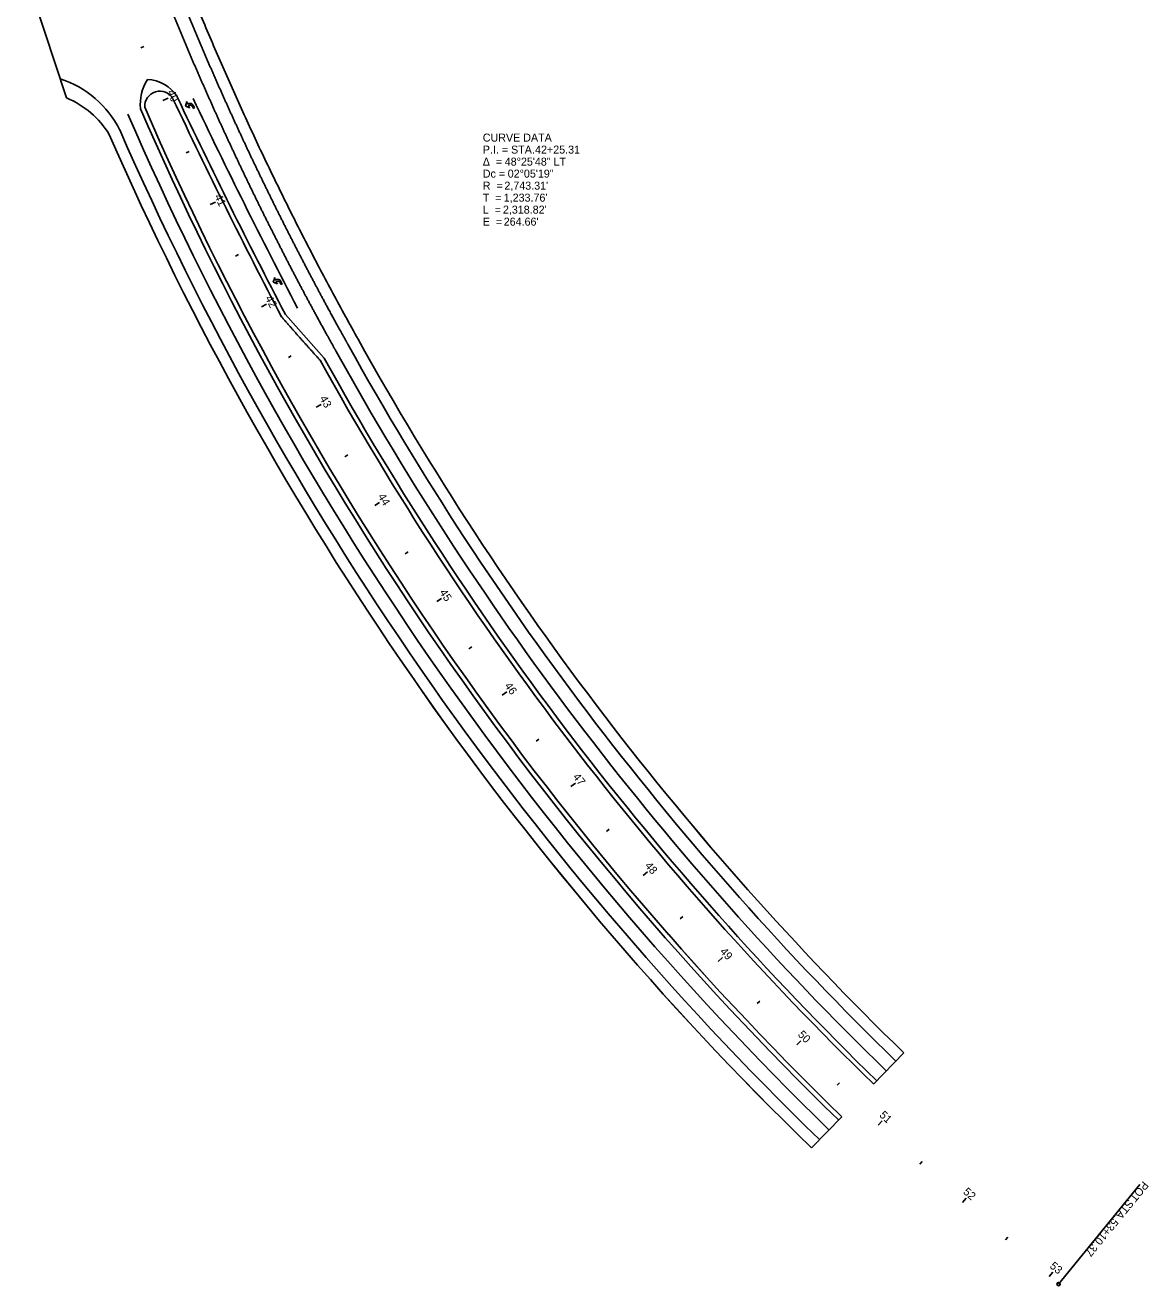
# Model space of a CAD drawing. Extents: x 76539 to 88870, y 518807 to 527554.
# Drawn here: x 87834 to 88817, y 518807 to 519909 of the extents above; entities that cross this region are included whole.
import ezdxf

# ---------------------------------------------------------------- set-up
doc = ezdxf.new("R2010")
doc.units = 0
for name, color, linetype in [('Default', 7, 'Continuous'), ('GE_P_Alignment_100_Cardinal_Points', 7, 'Continuous'), ('GE_P_Alignment_100_Curve_Data', 7, 'Continuous'), ('GE_P_Alignment_100_Stations', 7, 'Continuous'), ('PM_P_Cells', 7, 'Continuous'), ('PM_P_Channelizing_Line', 7, 'Continuous'), ('PM_P_Edge_Line', 7, 'Continuous'), ('PM_P_Lane_Line', 7, 'Continuous'), ('PV_P_Joint', 7, 'Continuous'), ('PV_P_Shoulder', 7, 'Continuous'), ('XS_P_Pavt_Surface', 7, 'Continuous')]:
    doc.layers.add(name, color=color, linetype=linetype)

msp = doc.modelspace()

# ---------------------------------------------------------------- linework, layer by layer
at = {"layer": 'Default'}
for points, degree in [([(87936.8, 520051.1), (87939.4, 520044), (87944.5, 520029.6), (87952.4, 520008.1), (87960.5, 519986.7), (87968.8, 519965.3), (87977.2, 519944), (87985.9, 519922.8), (87994.7, 519901.7), (88003.7, 519880.6), (88012.9, 519859.7), (88022.3, 519838.8), (88031.8, 519817.9), (88041.5, 519797.2), (88051.4, 519776.6), (88061.5, 519756), (88071.7, 519735.5), (88082.1, 519715.1), (88092.7, 519694.9), (88103.5, 519674.7), (88114.4, 519654.5), (88121.8, 519641.2), (88125.5, 519634.5)], 3), ([(87916.1, 520043.7), (87917.5, 520039.7), (87922.6, 520025.4), (87932.1, 519999.5), (87939.9, 519979), (87948.3, 519957.2), (87956.8, 519935.9), (87965.5, 519914.5), (87974.4, 519893.2), (87983.5, 519871.9), (87992.8, 519850.8), (88002.2, 519829.7), (88011.8, 519808.8), (88021.6, 519787.9), (88031.6, 519767), (88041.7, 519746.3), (88052.1, 519725.7), (88062.5, 519705.2), (88073.3, 519684.4), (88083.6, 519665.1), (88096.8, 519640.9), (88104.2, 519627.6), (88106.3, 519623.9)], 2), ([(87927.4, 520047.8), (87928.8, 520043.7), (87933.9, 520029.5), (87943.4, 520003.7), (87951.1, 519983.3), (87959.5, 519961.6), (87967.9, 519940.3), (87976.6, 519919), (87985.5, 519897.8), (87994.5, 519876.7), (88003.7, 519855.7), (88013.1, 519834.7), (88022.7, 519813.8), (88032.4, 519793), (88042.4, 519772.3), (88052.5, 519751.6), (88062.8, 519731.1), (88073.2, 519710.7), (88084, 519690), (88094.2, 519670.8), (88107.3, 519646.6), (88114.7, 519633.5), (88116.8, 519629.7)], 2)]:
    msp.add_open_spline(points, degree=degree, dxfattribs=at)
at = {"layer": 'GE_P_Alignment_100_Cardinal_Points'}
msp.add_line((88737.9, 518808.1), (88809, 518895.3), dxfattribs=at)
msp.add_circle((88737.9, 518808.1), 1.5, dxfattribs=at)
at = {"layer": 'GE_P_Alignment_100_Stations'}
for p, q in [((87935.4, 519889.3), (87938.2, 519890.5)), ((87954.8, 519843.3), (87959.4, 519845.3)), ((87975.1, 519797.6), (87977.9, 519798.8)), ((87996.2, 519752.3), (88000.8, 519754.4)), ((88018.2, 519707.3), (88020.9, 519708.7)), ((88040.9, 519662.8), (88045.4, 519665.1)), ((88064.5, 519618.7), (88067.1, 519620.1)), ((88088.9, 519575.1), (88093.2, 519577.5)), ((88114, 519531.8), (88116.6, 519533.4)), ((88140, 519489.1), (88144.2, 519491.7)), ((88166.7, 519446.8), (88169.2, 519448.5)), ((88194.2, 519405.1), (88198.3, 519407.8)), ((88222.4, 519363.8), (88224.9, 519365.5)), ((88251.4, 519323.1), (88255.4, 519326)), ((88281.1, 519282.9), (88283.5, 519284.7)), ((88311.6, 519243.2), (88315.5, 519246.3)), ((88342.7, 519204.1), (88345.1, 519206)), ((88374.6, 519165.6), (88378.4, 519168.8)), ((88407.2, 519127.6), (88409.4, 519129.6)), ((88440.4, 519090.3), (88444.1, 519093.7)), ((88474.4, 519053.6), (88476.6, 519055.6)), ((88509, 519017.5), (88512.5, 519021)), ((88544.2, 518982), (88546.3, 518984.2)), ((88580.1, 518947.2), (88583.6, 518950.8)), ((88616.6, 518913.1), (88618.7, 518915.3)), ((88653.8, 518879.6), (88657.1, 518883.3)), ((88691.5, 518846.8), (88693.4, 518849.1)), ((88729.8, 518814.7), (88733, 518818.5))]:
    msp.add_line(p, q, dxfattribs=at)
at = {"layer": 'PM_P_Cells'}
for p, q in [((87975.9, 519842.5), (87974.5, 519838.4)), ((87975.9, 519842.5), (87975.9, 519842.5)), ((87976.3, 519840.2), (87975.9, 519842.5)), ((87974.5, 519838.4), (87978.3, 519836.9)), ((87976.9, 519840.5), (87976.3, 519840.2)), ((87977, 519838.8), (87977.6, 519839.1)), ((87978.3, 519836.9), (87977, 519838.8)), ((87979.4, 519835.3), (87979.4, 519835.3)), ((87980.7, 519838.1), (87981.5, 519836.4)), ((87982.4, 519836.8), (87981.3, 519839.1)), ((87981.5, 519836.4), (87982.4, 519836.8)), ((88052.6, 519688.5), (88051.3, 519684.4)), ((88052.6, 519688.5), (88052.6, 519688.5)), ((88053, 519686.2), (88052.6, 519688.5)), ((88051.3, 519684.4), (88055, 519682.9)), ((88053.6, 519686.5), (88053, 519686.2)), ((88053.7, 519684.8), (88054.3, 519685.1)), ((88055, 519682.9), (88053.7, 519684.8)), ((88056.2, 519681.3), (88056.2, 519681.3)), ((88057.4, 519684), (88058.3, 519682.4)), ((88059.1, 519682.8), (88058, 519685)), ((88058.3, 519682.4), (88059.1, 519682.8))]:
    msp.add_line(p, q, dxfattribs=at)
for centre, radius, end in [((87978.4, 519837.6), 3.28, 117.392), ((87978.6, 519837), 2.3, 116.4835), ((88055.1, 519683.6), 3.28, 117.392), ((88055.4, 519683), 2.3, 116.4835)]:
    msp.add_arc(centre, radius, 26.4835, end, dxfattribs=at)
at = {"layer": 'PM_P_Channelizing_Line'}
msp.add_arc((92717.6, 522090.4), 5241.6, 205.3632, 207.6038, dxfattribs=at)
at = {"layer": 'PM_P_Edge_Line'}
msp.add_line((88062, 519656.2), (88095.8, 519618.1), dxfattribs=at)
for centre, radius, start, end in [((87837.8, 519778), 88.6, 26.4768, 72.1065), ((87977.1, 519839.8), 42, 148.5921, 185.0887), ((87940.3, 519829.9), 31.8, 31.9322, 88.2373), ((92717.6, 522090.4), 5253.6, 205.2828, 207.6038), ((90472.1, 520933.7), 2764.1, 203.3971, 225.813), ((90472.1, 520933.7), 2788.1, 203.598, 225.813), ((90472.1, 520933.7), 2692.2, 208.9703, 225.8127), ((90472.1, 520933.7), 2716.2, 208.9703, 225.8127)]:
    msp.add_arc(centre, radius, start, end, dxfattribs=at)
at = {"layer": 'PM_P_Lane_Line'}
for radius, start, end in [(2776.1, 203.3971, 225.813), (2704.2, 208.9703, 225.8127)]:
    msp.add_arc((90472.1, 520933.7), radius, start, end, dxfattribs=at)
at = {"layer": 'PV_P_Joint'}
for p, q in [((87834.5, 519955), (87870.6, 519845.6)), ((88602.6, 519010.4), (88576.1, 518983.1)), ((88548.3, 518954.5), (88521.8, 518927.2))]:
    msp.add_line(p, q, dxfattribs=at)
at = {"layer": 'PV_P_Shoulder'}
for centre, radius, start, end in [((87840.4, 519772.6), 79, 31.2308, 67.5512), ((87952.2, 519838.2), 13.3, 30.6146, 182.6353), ((92717.6, 522090.4), 5257.6, 205.2828, 207.6038), ((90472.1, 520933.7), 2760.1, 203.3971, 225.813), ((90472.1, 520933.7), 2798.1, 203.598, 225.813), ((90472.1, 520933.7), 2682.2, 208.9703, 225.8127), ((90472.1, 520933.7), 2720.2, 208.9703, 225.8127)]:
    msp.add_arc(centre, radius, start, end, dxfattribs=at)
msp.add_open_spline([(88092.3, 519616.1), (88091.7, 519616.8), (88090.6, 519618), (88088.9, 519619.9), (88087.2, 519621.8), (88085.5, 519623.7), (88083.8, 519625.6), (88082.1, 519627.5), (88080.4, 519629.4), (88078.7, 519631.3), (88077, 519633.2), (88075.3, 519635.1), (88073.6, 519637), (88071.9, 519638.9), (88070.2, 519640.9), (88068.5, 519642.8), (88066.9, 519644.7), (88065.2, 519646.6), (88063.5, 519648.5), (88061.8, 519650.5), (88060.1, 519652.4), (88059, 519653.7), (88058.5, 519654.3)], degree=3, dxfattribs=at)
at = {"layer": 'XS_P_Pavt_Surface'}
for p, q in [((87870.6, 519845.6), (87834.5, 519955)), ((88602.6, 519010.4), (88576.1, 518983.1)), ((88548.3, 518954.5), (88521.8, 518927.2))]:
    msp.add_line(p, q, dxfattribs=at)
for centre, radius, start, end in [((87840.4, 519772.6), 79, 31.2308, 67.5512), ((87952.2, 519838.2), 13.3, 30.6146, 182.6353), ((92717.6, 522090.4), 5257.6, 205.2828, 207.6038), ((90472.1, 520933.7), 2760.1, 203.3971, 225.8131), ((90472.1, 520933.7), 2798.1, 203.598, 225.8133), ((90472.1, 520933.7), 2682.2, 208.9703, 225.8129), ((90472.1, 520933.7), 2720.2, 208.9703, 225.813)]:
    msp.add_arc(centre, radius, start, end, dxfattribs=at)
for points in [[(87936.8, 520051.1), (87939.4, 520044), (87944.5, 520029.6), (87952.4, 520008.1), (87960.5, 519986.7), (87968.8, 519965.3), (87977.2, 519944), (87985.9, 519922.8), (87994.7, 519901.7), (88003.7, 519880.6), (88012.9, 519859.7), (88022.3, 519838.8), (88031.8, 519817.9), (88041.5, 519797.2), (88051.4, 519776.6), (88061.5, 519756), (88071.7, 519735.5), (88082.1, 519715.1), (88092.7, 519694.9), (88103.5, 519674.7), (88114.4, 519654.5), (88121.8, 519641.2), (88125.5, 519634.5)], [(88092.3, 519616.1), (88091.7, 519616.8), (88090.6, 519618), (88088.9, 519619.9), (88087.2, 519621.8), (88085.5, 519623.7), (88083.8, 519625.6), (88082.1, 519627.5), (88080.4, 519629.4), (88078.7, 519631.3), (88077, 519633.2), (88075.3, 519635.1), (88073.6, 519637), (88071.9, 519638.9), (88070.2, 519640.9), (88068.5, 519642.8), (88066.9, 519644.7), (88065.2, 519646.6), (88063.5, 519648.5), (88061.8, 519650.5), (88060.1, 519652.4), (88059, 519653.7), (88058.5, 519654.3)]]:
    msp.add_open_spline(points, degree=3, dxfattribs=at)

# ---------------------------------------------------------------- texts
at = {"layer": 'GE_P_Alignment_100_Cardinal_Points'}
for s, p in [('POT', (88811.8, 518898.6)), (' STA. ', (88800.4, 518884.7)), ('53+10.37', (88785.5, 518866.3))]:
    msp.add_text(s, height=7, rotation=230.7887, dxfattribs=at).set_placement(p)
at = {"layer": 'GE_P_Alignment_100_Curve_Data'}
for s, p in [('CURVE DATA', (88234.5, 519807.4)), ('P.I. = STA. ', (88234.5, 519796.9)), ('42+25.31', (88280.2, 519796.9)), ('Δ  = ', (88234.5, 519786.4)), ('48°25\'48" LT', (88253.7, 519786.4)), ('Dc = ', (88234.5, 519775.9)), ('02°05\'19"', (88256.3, 519775.9)), ('R  = ', (88234.5, 519765.4)), ("2,743.31'", (88253.4, 519765.4)), ('T  = ', (88234.5, 519754.9)), ("1,233.76'", (88252.8, 519754.9)), ('L  = ', (88234.5, 519744.4)), ("2,318.82'", (88252.1, 519744.4)), ('E  = ', (88234.5, 519733.9)), ("264.66'", (88252.8, 519733.9))]:
    msp.add_text(s, height=7, dxfattribs=at).set_placement(p)
at = {"layer": 'GE_P_Alignment_100_Stations'}
for s, rotation, p in [('40', 293.4208, (87958.4, 519850.9)), ('41', 295.5094, (87999.7, 519759.5)), ('42', 297.5979, (88044, 519670.5)), ('43', 299.6865, (88091.6, 519582.8)), ('44', 301.7751, (88142.5, 519497)), ('45', 303.8636, (88196.3, 519413.1)), ('46', 305.9522, (88253.2, 519331.3)), ('47', 308.0408, (88312.9, 519251.6)), ('48', 310.1293, (88375.8, 519173.8)), ('49', 312.2179, (88441.4, 519098.6)), ('50', 314.3065, (88509.5, 519025.8)), ('51', 316.395, (88580.7, 518955.3)), ('52', 318.4836, (88653.9, 518887.9)), ('53', 320.5721, (88729.6, 518822.9))]:
    msp.add_text(s, height=7, rotation=rotation, dxfattribs=at).set_placement(p)

doc.saveas('drawing.dxf')
